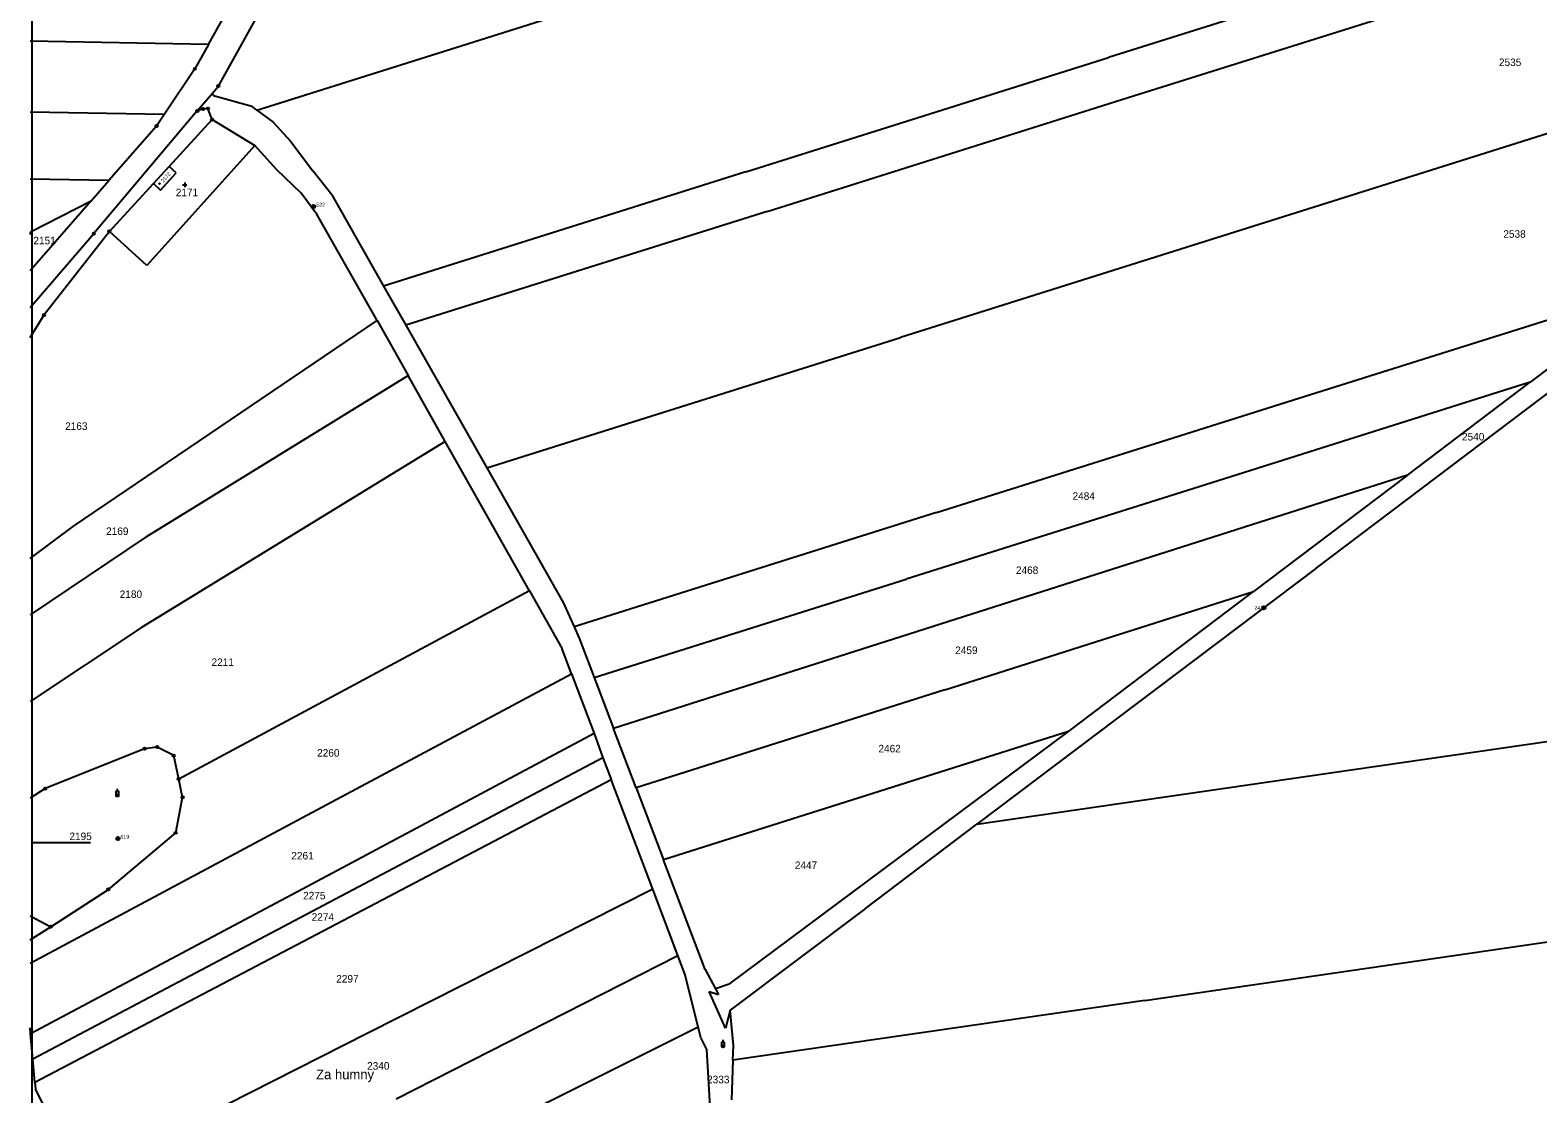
# Model space of a CAD drawing. Extents: x -565355 to -564154, y -1097649 to -1095548.
# Drawn here: x -565344 to -564662, y -1096921 to -1096441 of the extents above; entities that cross this region are included whole.
import ezdxf

# ---------------------------------------------------------------- set-up
doc = ezdxf.new("R2010")
doc.units = 0
for name, color, linetype in [('Vrstva 1', 7, 'Continuous'), ('Vrstva 15', 7, 'Continuous'), ('Vrstva 17', 7, 'Continuous'), ('Vrstva 18', 7, 'Continuous'), ('Vrstva 19', 7, 'Continuous'), ('Vrstva 24', 7, 'Continuous'), ('Vrstva 25', 7, 'Continuous'), ('Vrstva 63', 7, 'Continuous')]:
    doc.layers.add(name, color=color, linetype=linetype)

msp = doc.modelspace()

# ---------------------------------------------------------------- linework, layer by layer
at = {"layer": 'Vrstva 1'}
for p, q in [((-565258.49, -1096465.86), (-565216.9, -1096390.96)), ((-564692.48, -1096401.4), (-564856.27, -1096453.02)), ((-565262.99, -1096447.02), (-565243.5, -1096412.03)), ((-564847.26, -1096471.1), (-564683.96, -1096419.71)), ((-565241.07, -1096476.71), (-565077.05, -1096425.03)), ((-565262.99, -1096447.02), (-565343.59, -1096445.56)), ((-565262.99, -1096447.02), (-565269.14, -1096458.08)), ((-565020.06, -1096504.63), (-564856.27, -1096453.02)), ((-565269.14, -1096458.08), (-565282.85, -1096478.59)), ((-565261.2, -1096469.05), (-565258.49, -1096465.86)), ((-564576.32, -1096461.67), (-564763.28, -1096520.59)), ((-565268.04, -1096477.1), (-565261.2, -1096469.05)), ((-565260.7, -1096470.15), (-565261.2, -1096469.05)), ((-565260.7, -1096470.15), (-565243.38, -1096475)), ((-565010.55, -1096522.5), (-564847.26, -1096471.1)), ((-565343.59, -1096477.5), (-565282.85, -1096478.59)), ((-565268.04, -1096477.1), (-565314.82, -1096532.53)), ((-565282.85, -1096478.59), (-565286.44, -1096483.96)), ((-565280.78, -1096502.26), (-565261.34, -1096481.04)), ((-565265.42, -1096476.19), (-565268.04, -1096477.1)), ((-565263.24, -1096476.01), (-565265.42, -1096476.19)), ((-565261.34, -1096481.04), (-565263.24, -1096476.01)), ((-565261.34, -1096481.04), (-565241.98, -1096492.65)), ((-565241.07, -1096476.71), (-565243.38, -1096475)), ((-565241.07, -1096476.71), (-565233.76, -1096482.11)), ((-565286.44, -1096483.96), (-565307.96, -1096508.59)), ((-565233.76, -1096482.11), (-565225.98, -1096490.71)), ((-565241.98, -1096492.65), (-565290.82, -1096546.91)), ((-565232.07, -1096503.65), (-565241.98, -1096492.65)), ((-565225.98, -1096490.71), (-565215.8, -1096504.19)), ((-565307.96, -1096508.59), (-565343.59, -1096507.95)), ((-565287.9, -1096509.92), (-565280.78, -1096502.26)), ((-565284.66, -1096512.93), (-565277.58, -1096505.1)), ((-565277.58, -1096505.1), (-565280.78, -1096502.26)), ((-565221.12, -1096514.32), (-565232.07, -1096503.65)), ((-565207.25, -1096515.04), (-565215.8, -1096504.19)), ((-565020.06, -1096504.63), (-565183.86, -1096556.24)), ((-565315.99, -1096517.78), (-565307.96, -1096508.59)), ((-565307.78, -1096531.54), (-565287.9, -1096509.92)), ((-565287.9, -1096509.92), (-565284.66, -1096512.93)), ((-565213.82, -1096524), (-565221.12, -1096514.32)), ((-565207.25, -1096515.04), (-565183.86, -1096556.24)), ((-565315.99, -1096517.78), (-565343.59, -1096549.42)), ((-565343.11, -1096531.65), (-565315.99, -1096517.78)), ((-564763.28, -1096520.59), (-564950.25, -1096579.5)), ((-565186.82, -1096571.82), (-565213.82, -1096524)), ((-565010.55, -1096522.5), (-565173.84, -1096573.89)), ((-565343.59, -1096532.97), (-565343.11, -1096531.65)), ((-565343.59, -1096565.98), (-565314.82, -1096532.53)), ((-565307.78, -1096531.54), (-565337.32, -1096569.27)), ((-565290.82, -1096546.91), (-565307.78, -1096531.54)), ((-564770.19, -1096606.92), (-564606.39, -1096555.31)), ((-565183.86, -1096556.24), (-565173.84, -1096573.89)), ((-565343.59, -1096579.53), (-565337.32, -1096569.27)), ((-564762.56, -1096683.78), (-564609.37, -1096568.16)), ((-564626.03, -1096569.52), (-564665.67, -1096599.71)), ((-565324.06, -1096664.76), (-565186.82, -1096571.82)), ((-565186.82, -1096571.82), (-565172.79, -1096596.67)), ((-565173.84, -1096573.89), (-565137.21, -1096638.41)), ((-565137.21, -1096638.41), (-564950.25, -1096579.5)), ((-565291.15, -1096669.5), (-565172.79, -1096596.67)), ((-565155.94, -1096626.51), (-565172.79, -1096596.67)), ((-564665.67, -1096599.71), (-564806.68, -1096644.17)), ((-564721, -1096641.66), (-564665.67, -1096599.71)), ((-564933.98, -1096658.53), (-564770.19, -1096606.92)), ((-565155.94, -1096626.51), (-565293.28, -1096710.42)), ((-565117.9, -1096693.85), (-565155.94, -1096626.51)), ((-565137.21, -1096638.41), (-565102.67, -1096699.24)), ((-564806.68, -1096644.17), (-564947.69, -1096688.62)), ((-564721, -1096641.66), (-564900.44, -1096698.87)), ((-564721, -1096641.66), (-564790.63, -1096694.26)), ((-565343.59, -1096679.37), (-565324.06, -1096664.76)), ((-564933.98, -1096658.53), (-565097.78, -1096710.14)), ((-565291.15, -1096669.5), (-565343.59, -1096704.81)), ((-564762.56, -1096683.78), (-564915.74, -1096799.4)), ((-565088.7, -1096733.08), (-564947.69, -1096688.62)), ((-565117.9, -1096693.85), (-565276.44, -1096778.95)), ((-565117.9, -1096693.85), (-565103.09, -1096720.12)), ((-565102.67, -1096699.24), (-565097.78, -1096710.14)), ((-564900.44, -1096698.87), (-565079.89, -1096756.08)), ((-564930.17, -1096738.6), (-564790.63, -1096694.26)), ((-564874.28, -1096757.42), (-564790.63, -1096694.26)), ((-565293.28, -1096710.42), (-565343.59, -1096743.97)), ((-565097.78, -1096710.14), (-565095.49, -1096715.25)), ((-565095.49, -1096715.25), (-565088.7, -1096733.08)), ((-565098.91, -1096731.35), (-565103.09, -1096720.12)), ((-565222.7, -1096797.48), (-565098.91, -1096731.35)), ((-565098.91, -1096731.35), (-565088.71, -1096758.4)), ((-565088.7, -1096733.08), (-565079.89, -1096756.08)), ((-564930.17, -1096738.6), (-565069.71, -1096782.95)), ((-564755.84, -1096776.15), (-564595.94, -1096752.9)), ((-565088.71, -1096758.4), (-565216.04, -1096826.22)), ((-565088.71, -1096758.4), (-565084.69, -1096769.34)), ((-565069.71, -1096782.95), (-565079.89, -1096756.08)), ((-564874.28, -1096757.42), (-565057.36, -1096815.38)), ((-564950.92, -1096814.58), (-564874.28, -1096757.42)), ((-565291.86, -1096765.25), (-565336.81, -1096783.24)), ((-565286.16, -1096764.5), (-565291.86, -1096765.25)), ((-565278.7, -1096768.37), (-565286.16, -1096764.5)), ((-565276.44, -1096778.95), (-565278.7, -1096768.37)), ((-565084.69, -1096769.34), (-565213.55, -1096837.39)), ((-565084.69, -1096769.34), (-565080.96, -1096779.17)), ((-565274.67, -1096787.24), (-565276.44, -1096778.95)), ((-565211.22, -1096847.51), (-565080.96, -1096779.17)), ((-565062.18, -1096828.63), (-565080.96, -1096779.17)), ((-564915.74, -1096799.4), (-564755.84, -1096776.15)), ((-565336.81, -1096783.24), (-565343.59, -1096787.54)), ((-565277.8, -1096803.23), (-565274.67, -1096787.24)), ((-565069.71, -1096782.95), (-565057.36, -1096815.38)), ((-565343.59, -1096862.05), (-565222.7, -1096797.48)), ((-564966.04, -1096837.39), (-564915.74, -1096799.4)), ((-565308.21, -1096828.78), (-565277.8, -1096803.23)), ((-565027.71, -1096871.61), (-564950.92, -1096814.58)), ((-565038.5, -1096864.91), (-565057.36, -1096815.38)), ((-565216.04, -1096826.22), (-565343.36, -1096894.05)), ((-565062.18, -1096828.63), (-565191.34, -1096893.95)), ((-565050.85, -1096858.7), (-565062.18, -1096828.63)), ((-565334.29, -1096845.64), (-565308.21, -1096828.78)), ((-565343.59, -1096840.73), (-565334.29, -1096845.64)), ((-565213.55, -1096837.39), (-565342.41, -1096905.44)), ((-564966.04, -1096837.39), (-565027.19, -1096883.39)), ((-565343.59, -1096851.54), (-565334.29, -1096845.64)), ((-565341.49, -1096915.85), (-565211.22, -1096847.51)), ((-564839.78, -1096878.94), (-564653.63, -1096851.88)), ((-565178.1, -1096923.38), (-565050.85, -1096858.7)), ((-565047.6, -1096867.38), (-565050.85, -1096858.7)), ((-565041.65, -1096891.05), (-565047.6, -1096867.38)), ((-565038.5, -1096864.91), (-565033.9, -1096873.69)), ((-565029.26, -1096891.53), (-565036.68, -1096874.85)), ((-565036.68, -1096874.85), (-565032.51, -1096876.34)), ((-565027.71, -1096871.61), (-565033.9, -1096873.69)), ((-565033.9, -1096873.69), (-565032.51, -1096876.34)), ((-564839.78, -1096878.94), (-565025.94, -1096906.01)), ((-565027.19, -1096883.39), (-565029.26, -1096891.53)), ((-565025.68, -1096899.26), (-565027.19, -1096883.39)), ((-565343.36, -1096894.05), (-565343.59, -1096891.34)), ((-565342.41, -1096905.44), (-565343.36, -1096894.05)), ((-565191.34, -1096893.95), (-565320.5, -1096959.27)), ((-565041.65, -1096891.05), (-565166.5, -1096953.32)), ((-565040.5, -1096895.66), (-565041.65, -1096891.05)), ((-565037.8, -1096901.06), (-565040.5, -1096895.66)), ((-565036.11, -1096929.37), (-565037.8, -1096901.06)), ((-565025.94, -1096906.01), (-565025.68, -1096899.26)), ((-565341.49, -1096915.85), (-565342.41, -1096905.44)), ((-565025.94, -1096906.01), (-565026.61, -1096923.85)), ((-565341.49, -1096915.85), (-565341.23, -1096919.07)), ((-565320.5, -1096959.27), (-565341.23, -1096919.07))]:
    msp.add_line(p, q, dxfattribs=at)
at = {"layer": 'Vrstva 24'}
for centre, radius in [((-565269.14, -1096458.08), 0.5), ((-565269.14, -1096458.08), 0.0327), ((-565258.49, -1096465.86), 0.5), ((-565258.49, -1096465.86), 0.0327), ((-565268.04, -1096477.1), 0.5), ((-565268.04, -1096477.1), 0.0327), ((-565265.42, -1096476.19), 0.5), ((-565265.42, -1096476.19), 0.0327), ((-565263.24, -1096476.01), 0.5), ((-565263.24, -1096476.01), 0.0327), ((-565261.34, -1096481.04), 0.5), ((-565261.34, -1096481.04), 0.0327), ((-565286.44, -1096483.96), 0.5), ((-565286.44, -1096483.96), 0.0327), ((-565215.5, -1096520.29), 0.75), ((-565215.5, -1096520.29), 0.0327), ((-565314.82, -1096532.53), 0.5), ((-565314.82, -1096532.53), 0.0327), ((-565307.78, -1096531.54), 0.5), ((-565307.78, -1096531.54), 0.0327), ((-565337.32, -1096569.27), 0.5), ((-565337.32, -1096569.27), 0.0327), ((-564785.96, -1096701.58), 0.75), ((-564785.96, -1096701.58), 0.0327), ((-565291.86, -1096765.25), 0.5), ((-565291.86, -1096765.25), 0.0327), ((-565286.16, -1096764.5), 0.5), ((-565286.16, -1096764.5), 0.0327), ((-565278.7, -1096768.37), 0.5), ((-565278.7, -1096768.37), 0.0327), ((-565276.44, -1096778.95), 0.5), ((-565276.44, -1096778.95), 0.0327), ((-565336.81, -1096783.24), 0.5), ((-565336.81, -1096783.24), 0.0327), ((-565274.67, -1096787.24), 0.5), ((-565274.67, -1096787.24), 0.0327), ((-565303.94, -1096805.87), 0.75), ((-565303.94, -1096805.87), 0.0327), ((-565277.8, -1096803.23), 0.5), ((-565277.8, -1096803.23), 0.0327), ((-565308.21, -1096828.78), 0.5), ((-565308.21, -1096828.78), 0.0327), ((-565334.29, -1096845.64), 0.5), ((-565334.29, -1096845.64), 0.0327)]:
    msp.add_circle(centre, radius, dxfattribs=at)
at = {"layer": 'Vrstva 25'}
for p, q in [((-565274.73, -1096510.51), (-565272.73, -1096510.51)), ((-565273.73, -1096509.51), (-565273.73, -1096511.51)), ((-565304.14, -1096784.4), (-565304.14, -1096783.4)), ((-565030.43, -1096897.74), (-565030.43, -1096896.74))]:
    msp.add_line(p, q, dxfattribs=at)
for points in [[(-565304.64, -1096786.4), (-565304.64, -1096784.4), (-565303.64, -1096784.4), (-565303.64, -1096786.4)], [(-565030.93, -1096899.74), (-565030.93, -1096897.74), (-565029.93, -1096897.74), (-565029.93, -1096899.74)]]:
    msp.add_lwpolyline(points, dxfattribs=at)
for centre, radius in [((-565285.17, -1096509.99), 0.175), ((-565304.14, -1096786.4), 0.5), ((-565304.14, -1096786.4), 0.05), ((-565030.43, -1096899.74), 0.5), ((-565030.43, -1096899.74), 0.05)]:
    msp.add_circle(centre, radius, dxfattribs=at)
at = {"layer": 'Vrstva 63'}
for p, q in [((-565342.77, -1095547.8), (-565342.77, -1097647.8)), ((-565316.33, -1096807.8), (-565342.77, -1096807.8))]:
    msp.add_line(p, q, dxfattribs=at)

# ---------------------------------------------------------------- texts
at = {"layer": 'Vrstva 15'}
msp.add_text('Za humny', height=4.4, dxfattribs=at).set_placement((-565214.32, -1096914.57))
at = {"layer": 'Vrstva 17'}
for s, p in [('522', (-565214.31, -1096520.28)), ('241', (-564790.18, -1096702.43)), ('519', (-565302.75, -1096805.86))]:
    msp.add_text(s, height=1.7, dxfattribs=at).set_placement(p)
at = {"layer": 'Vrstva 18'}
for s, p in [('2535', (-564679.73, -1096456.84)), ('2171', (-565277.76, -1096515.62)), ('2151', (-565342.13, -1096537.36)), ('2538', (-564677.74, -1096534.41)), ('2163', (-565327.78, -1096621.2)), ('2540', (-564696.43, -1096625.99)), ('2484', (-564872.46, -1096652.8)), ('2169', (-565309.27, -1096668.68)), ('2468', (-564898.04, -1096686.3)), ('2180', (-565303.12, -1096697.14)), ('2459', (-564925.48, -1096722.46)), ('2211', (-565261.61, -1096727.86)), ('2260', (-565213.89, -1096768.81)), ('2462', (-564960.19, -1096766.89)), ('2195', (-565325.84, -1096806.52)), ('2261', (-565225.55, -1096815.28)), ('2447', (-564997.98, -1096819.59)), ('2275', (-565220.23, -1096833.3)), ('2274', (-565216.36, -1096842.96)), ('2297', (-565205.25, -1096870.87)), ('2340', (-565191.3, -1096910.23)), ('2333', (-565037.64, -1096916.38))]:
    msp.add_text(s, height=3.4, dxfattribs=at).set_placement(p)
at = {"layer": 'Vrstva 19'}
msp.add_text('2172', height=1.7, rotation=47.7, dxfattribs=at).set_placement((-565283.44, -1096509.62))

doc.saveas('drawing.dxf')
